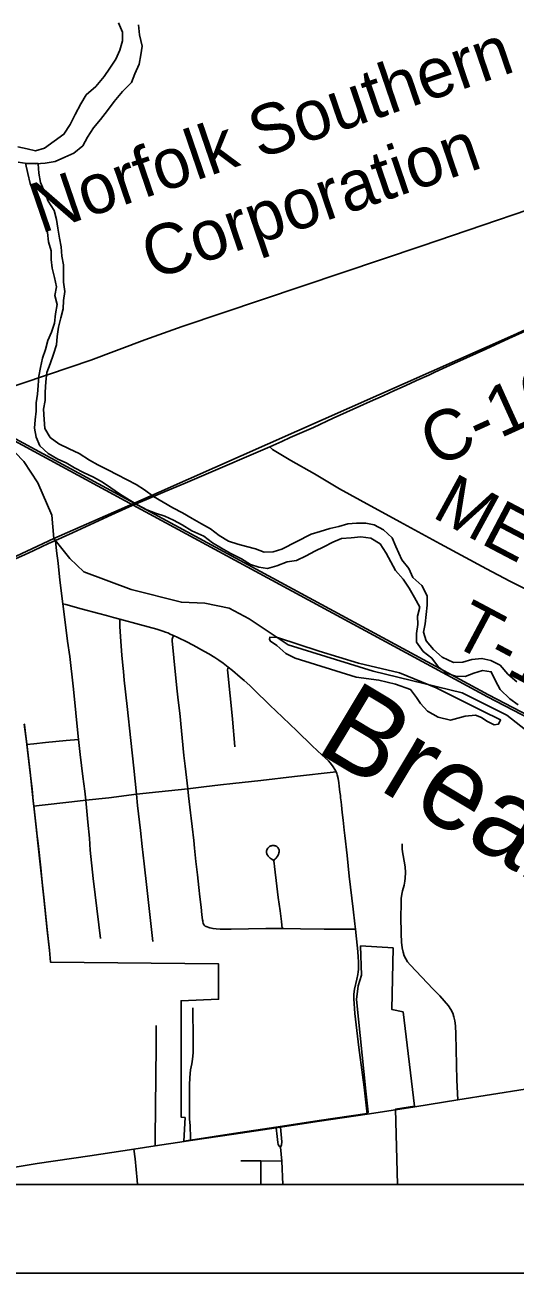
# Model space of a CAD drawing. Extents: x 0 to 34, y 0 to 22.
# Drawn here: x 3.04 to 3.593, y 14 to 15.41 of the extents above; entities that cross this region are included whole.
import ezdxf

# ---------------------------------------------------------------- set-up
doc = ezdxf.new("R2010")
doc.units = 0
for name, color, linetype in [('GM_X_City_Street', 7, 'Continuous'), ('GM_X_Corporation', 7, 'Continuous'), ('GM_X_County_Road', 7, 'Continuous'), ('GM_X_County_Road_Text', 7, 'Continuous'), ('GM_X_Major_River', 7, 'Continuous'), ('GM_X_Minor_Lake', 7, 'Continuous'), ('GM_X_Minor_River', 7, 'Continuous'), ('GM_X_Minor_River_Text', 7, 'Continuous'), ('GM_X_Rail_Line', 7, 'Continuous'), ('GM_X_Rail_Line_Text', 7, 'Continuous'), ('GM_X_State_Route', 7, 'Continuous'), ('GM_X_Township_Road', 7, 'Continuous'), ('GM_X_Township_Road_Text', 7, 'Continuous'), ('SH_Data', 7, 'Continuous')]:
    doc.layers.add(name, color=color, linetype=linetype)

msp = doc.modelspace()

# ---------------------------------------------------------------- linework, layer by layer
at = {"layer": 'GM_X_City_Street'}
for points in [[(3.1866, 14.1436), (3.1865, 14.1524), (3.1876, 14.2567), (3.1876, 14.2797)], [(3.3284, 14.1423), (3.3269, 14.1434), (3.3258, 14.1451), (3.3253, 14.1474), (3.3245, 14.1543), (3.3233, 14.1641)], [(3.3284, 14.1423), (3.3294, 14.145), (3.3296, 14.1484), (3.3281, 14.1649)], [(3.1668, 14.1), (3.1665, 14.1049), (3.164, 14.129), (3.1627, 14.1401)], [(3.3308, 14.1), (3.3298, 14.1265), (3.3284, 14.1423)], [(3.2836, 14.1268), (3.3061, 14.1267), (3.3298, 14.1265)], [(3.3062, 14.1), (3.3061, 14.1196), (3.3061, 14.1267)]]:
    msp.add_lwpolyline(points, dxfattribs=at)
at = {"layer": 'GM_X_Corporation'}
for points in [[(4.718, 17.4962), (3.7119, 17.4934), (3.5801, 17.4924), (3.4708, 17.4915), (3.0456, 17.4894), (2.6352, 17.4929), (2.5812, 17.4925), (2.1449, 17.4882), (2.1, 17.4875), (2.1, 14.1), (5.0398, 14.1)], [(2.1, 14.1), (3.4603, 14.1), (3.458, 14.1851), (3.4797, 14.1885), (3.4667, 14.2951), (3.4539, 14.2978), (3.4555, 14.3673), (3.4187, 14.3696), (3.4199, 14.3367), (3.416, 14.3246), (3.414, 14.3091), (3.4247, 14.2056), (3.4272, 14.1818), (3.4261, 14.1803), (3.372, 14.1723), (3.3279, 14.1654), (3.3231, 14.1647), (3.2753, 14.1575), (3.2265, 14.1501), (3.2191, 14.149), (3.2205, 14.1756), (3.216, 14.1762), (3.2159, 14.3077), (3.2583, 14.3094), (3.2581, 14.3495), (3.0684, 14.3512), (3.0671, 14.365), (3.0646, 14.3881), (3.0607, 14.4246), (3.0593, 14.4383), (3.0572, 14.4586), (3.0541, 14.486), (3.0524, 14.5009), (3.0494, 14.5281), (3.0488, 14.5337), (3.0473, 14.5479), (3.0453, 14.566), (3.0415, 14.5979), (3.0387, 14.6201)]]:
    msp.add_lwpolyline(points, dxfattribs=at)
at = {"layer": 'GM_X_County_Road'}
for points in [[(3.3161, 14.9336), (3.3297, 14.9398), (3.3393, 14.944), (3.3524, 14.9497), (3.3655, 14.9554), (3.3879, 14.9659), (3.4178, 14.9796), (3.4297, 14.9849), (3.4444, 14.9914), (3.4569, 14.9971), (3.4656, 15.0011), (3.4746, 15.0051), (3.482, 15.0084), (3.4959, 15.0147), (3.5017, 15.0174), (3.5115, 15.022), (3.5241, 15.0277), (3.5385, 15.0341), (3.5604, 15.0438), (3.5862, 15.0559), (3.6122, 15.0678)], [(3.0739, 14.8277), (3.0933, 14.8365), (3.1375, 14.8568), (3.1607, 14.8672), (3.1767, 14.8742), (3.1978, 14.883), (3.2204, 14.8925), (3.2441, 14.9027), (3.2652, 14.9117), (3.2899, 14.9223), (3.3161, 14.9336)], [(3.0264, 14.8058), (3.0389, 14.8117), (3.0488, 14.8162), (3.0583, 14.8206), (3.0662, 14.8242), (3.0739, 14.8277)]]:
    msp.add_lwpolyline(points, dxfattribs=at)
at = {"layer": 'GM_X_Major_River'}
for points in [[(3.0319, 15.2553), (3.0418, 15.2538), (3.052, 15.2535), (3.0622, 15.254), (3.0736, 15.256), (3.0845, 15.261), (3.0947, 15.2656), (3.1048, 15.2737), (3.1101, 15.2836), (3.1168, 15.2939), (3.1247, 15.3034), (3.1329, 15.3137), (3.1404, 15.324), (3.1498, 15.3351), (3.1599, 15.3454), (3.1636, 15.3549), (3.1685, 15.3659), (3.1703, 15.3766), (3.1721, 15.3864), (3.169, 15.3993), (3.1677, 15.4103)], [(3.1454, 15.4128), (3.1496, 15.4022), (3.1497, 15.3923), (3.1468, 15.3817), (3.1423, 15.3718), (3.1356, 15.3615), (3.1292, 15.352), (3.1198, 15.3409), (3.1086, 15.3313), (3.1026, 15.3211), (3.0962, 15.3093), (3.0906, 15.2978), (3.0835, 15.2868), (3.0726, 15.2791), (3.0617, 15.2711), (3.0515, 15.2679)], [(3.0515, 15.2679), (3.042, 15.2705), (3.0314, 15.2727)]]:
    msp.add_lwpolyline(points, dxfattribs=at)
at = {"layer": 'GM_X_Minor_Lake'}
msp.add_line((3.4626, 14.6783), (3.4163, 14.6893), dxfattribs=at)
msp.add_lwpolyline([(3.4163, 14.6893), (3.3719, 14.7027), (3.3249, 14.7182), (3.3162, 14.7185), (3.3158, 14.7159), (3.317, 14.714), (3.3242, 14.7091), (3.3341, 14.7001), (3.3447, 14.6949), (3.4138, 14.6734), (3.4392, 14.6698), (3.4581, 14.6654), (3.4752, 14.6595), (3.4821, 14.6504), (3.4863, 14.6436), (3.4943, 14.635), (3.5065, 14.6282), (3.5205, 14.6249), (3.5368, 14.6292), (3.5485, 14.6304), (3.5553, 14.6278), (3.5614, 14.6237), (3.5698, 14.6196), (3.5747, 14.6204), (3.5769, 14.625), (3.556, 14.6354), (3.5043, 14.6612), (3.4626, 14.6783)], dxfattribs=at)
at = {"layer": 'GM_X_Minor_River'}
msp.add_line((3.0543, 15.2536), (3.0403, 15.2541), dxfattribs=at)
for points in [[(3.0403, 15.2541), (3.0426, 15.2425), (3.0454, 15.2311), (3.05, 15.2201), (3.0554, 15.2099), (3.0577, 15.1986), (3.0616, 15.1872), (3.0651, 15.1759), (3.0663, 15.1653), (3.069, 15.1551), (3.0691, 15.1452), (3.0703, 15.1354), (3.0731, 15.1248), (3.075, 15.1145), (3.0732, 15.1047), (3.0759, 15.0944), (3.0741, 15.0838), (3.0731, 15.0732), (3.0694, 15.0633), (3.0653, 15.0538), (3.0627, 15.0435), (3.0594, 15.0336), (3.0572, 15.0234), (3.0554, 15.0135), (3.0543, 15.0029), (3.0536, 14.993), (3.0522, 14.9835), (3.0523, 14.974), (3.0512, 14.9642), (3.0505, 14.9547), (3.0521, 14.9444), (3.0564, 14.9346), (3.0659, 14.926), (3.0765, 14.9196), (3.086, 14.9155), (3.0955, 14.9099), (3.1058, 14.9046), (3.1168, 14.8994), (3.1271, 14.8938), (3.1366, 14.8874), (3.1465, 14.8803), (3.1571, 14.8736), (3.1666, 14.868), (3.1773, 14.8623), (3.1872, 14.8586), (3.1974, 14.8553), (3.2073, 14.8508), (3.2172, 14.8456), (3.2282, 14.8388), (3.2415, 14.8325), (3.2514, 14.825), (3.2616, 14.819), (3.2723, 14.813), (3.2841, 14.807), (3.2943, 14.8007), (3.3038, 14.7977), (3.3137, 14.7963), (3.3242, 14.799), (3.3356, 14.8036), (3.3465, 14.8052), (3.3571, 14.8103), (3.3669, 14.8156), (3.3774, 14.8207), (3.3872, 14.826), (3.3971, 14.8299), (3.408, 14.8308), (3.419, 14.832), (3.4304, 14.8305), (3.441, 14.8238), (3.4475, 14.8136), (3.4583, 14.794), (3.4667, 14.7842), (3.4736, 14.774), (3.4797, 14.7634), (3.4855, 14.7525), (3.4829, 14.7422), (3.4833, 14.7327), (3.4819, 14.7228), (3.482, 14.713), (3.4896, 14.7024), (3.4992, 14.6949), (3.5068, 14.6847), (3.5163, 14.678), (3.5258, 14.6743), (3.5368, 14.674), (3.5466, 14.6778), (3.5564, 14.6809), (3.5663, 14.6795), (3.5713, 14.6693), (3.5766, 14.6595), (3.5873, 14.6489), (3.5968, 14.6422)], [(3.434, 14.8454), (3.4246, 14.8472), (3.4143, 14.8475), (3.4045, 14.8467), (3.3943, 14.8435), (3.3841, 14.8412), (3.3731, 14.8381), (3.363, 14.835), (3.3298, 14.818), (3.32, 14.8149), (3.3097, 14.8144), (3.2999, 14.8185), (3.29, 14.8211), (3.2802, 14.8237), (3.2695, 14.827), (3.2589, 14.8334), (3.249, 14.8409), (3.2391, 14.8465), (3.2285, 14.8525), (3.2174, 14.8589), (3.2068, 14.8648), (3.1847, 14.8776), (3.1745, 14.8851), (3.165, 14.8911), (3.1551, 14.8963), (3.1433, 14.9023), (3.1338, 14.9071), (3.122, 14.9131), (3.1125, 14.9187), (3.1007, 14.9262), (3.0893, 14.9315), (3.0779, 14.9371), (3.068, 14.9442), (3.0619, 14.9544), (3.0614, 14.9646), (3.0606, 14.976), (3.0624, 14.9859), (3.0623, 14.9953), (3.063, 15.0071), (3.0641, 15.0177), (3.0681, 15.0272), (3.0718, 15.0383), (3.0752, 15.0489), (3.0758, 15.0584), (3.0773, 15.0687), (3.0802, 15.0793), (3.0828, 15.0896), (3.0831, 15.099), (3.0845, 15.1093), (3.0829, 15.1195), (3.0832, 15.1294), (3.0832, 15.1392), (3.0812, 15.1491), (3.0804, 15.1597), (3.0784, 15.1695), (3.0768, 15.1805), (3.0752, 15.1904), (3.0725, 15.2006), (3.0656, 15.2112), (3.0621, 15.221), (3.0571, 15.2323), (3.0551, 15.2429), (3.0543, 15.2532), (3.0543, 15.2536)], [(3.5951, 14.668), (3.5852, 14.6766), (3.5764, 14.6868), (3.5658, 14.692), (3.5559, 14.6946), (3.5446, 14.6934), (3.5344, 14.6903), (3.5238, 14.6898), (3.5109, 14.6958), (3.5013, 14.7044), (3.4929, 14.7142), (3.4898, 14.724), (3.4917, 14.7335), (3.4938, 14.7548), (3.4941, 14.7654), (3.4879, 14.7768), (3.4776, 14.7858), (3.4734, 14.796), (3.4654, 14.8058), (3.4584, 14.8209), (3.4546, 14.8307), (3.4447, 14.8398), (3.434, 14.8454)]]:
    msp.add_lwpolyline(points, dxfattribs=at)
at = {"layer": 'GM_X_Rail_Line'}
msp.add_line((3.0723, 14.8299), (3.1616, 14.8692), dxfattribs=at)
for points in [[(3.0008, 14.9933), (3.0663, 15.0153), (3.1139, 15.0316), (3.175, 15.0545), (3.2173, 15.0694), (3.4884, 15.1608), (3.6761, 15.2246)], [(3.1616, 14.8692), (3.5915, 15.0597), (3.6949, 15.1071), (3.7867, 15.1408), (3.9605, 15.1904), (4.0114, 15.1928), (4.2869, 15.2006), (4.3333, 15.1875), (4.5683, 15.0852), (4.7376, 15.04), (4.9105, 14.9964), (5.0522, 14.9674), (5.2111, 14.9619), (5.2822, 14.9606)], [(2.9606, 14.9721), (3.0091, 14.9466), (3.0383, 14.9172), (3.0542, 14.893), (3.0698, 14.8562), (3.0723, 14.8299)], [(4.594, 14.1158), (4.5467, 14.1314), (4.5029, 14.1512), (4.4554, 14.1733), (4.4129, 14.1964), (4.0324, 14.4067), (3.5622, 14.6511), (3.1618, 14.8678), (3.0276, 14.9405)], [(4.5947, 14.118), (4.5475, 14.1335), (4.5039, 14.1533), (4.4565, 14.1754), (4.414, 14.1984), (4.0335, 14.4087), (3.5633, 14.6532), (3.163, 14.8698), (3.0287, 14.9426)], [(2.1, 14.4871), (2.3619, 14.5917), (2.808, 14.7281), (3.0106, 14.8014), (3.0723, 14.8299)], [(3.0723, 14.8299), (3.0901, 14.8076), (3.1059, 14.7922), (3.1597, 14.7724), (3.2163, 14.758), (3.2426, 14.7571), (3.2702, 14.7513), (3.2929, 14.7393), (3.3369, 14.7099), (3.4328, 14.68), (3.5336, 14.6555), (3.5839, 14.6302), (3.6492, 14.5791), (3.7337, 14.5084), (3.8119, 14.4399), (3.8676, 14.3979), (4.0792, 14.1965), (4.1324, 14.1247), (4.148, 14.1)]]:
    msp.add_lwpolyline(points, dxfattribs=at)
at = {"layer": 'GM_X_State_Route'}
for p, q in [((3.4582, 14.1846), (3.4799, 14.1879)), ((3.4263, 14.1797), (3.4582, 14.1846))]:
    msp.add_line(p, q, dxfattribs=at)
for points in [[(3.4799, 14.1879), (3.5286, 14.1957), (3.6048, 14.2077), (3.6481, 14.2147), (3.7802, 14.2348), (3.9245, 14.2567)], [(3.2193, 14.1485), (3.2267, 14.1496), (3.2755, 14.157), (3.3233, 14.1641), (3.3281, 14.1649), (3.3722, 14.1717), (3.4263, 14.1797)], [(3.0084, 14.1167), (3.0191, 14.1181), (3.0352, 14.1206), (3.0535, 14.1236), (3.1129, 14.1326), (3.1627, 14.1401), (3.1866, 14.1436), (3.2193, 14.1485)]]:
    msp.add_lwpolyline(points, dxfattribs=at)
at = {"layer": 'GM_X_Township_Road'}
for points in [[(3.3161, 14.9336), (3.3177, 14.9319), (3.3193, 14.9305), (3.3228, 14.9282), (3.3398, 14.9181), (3.3666, 14.9029), (3.3951, 14.8863), (3.4184, 14.8733), (3.4631, 14.8489), (3.5088, 14.8239), (3.561, 14.7957), (3.5875, 14.7818), (3.6063, 14.7723)], [(3.0823, 14.7563), (3.0791, 14.7829), (3.0769, 14.802), (3.0752, 14.8162), (3.0739, 14.8277)], [(3.0823, 14.7563), (3.0859, 14.7553), (3.103, 14.7507), (3.123, 14.7453), (3.1316, 14.7429), (3.1394, 14.7408), (3.1466, 14.7388)], [(3.1, 14.603), (3.0979, 14.6251), (3.0963, 14.6411), (3.094, 14.6633), (3.0902, 14.6967), (3.0877, 14.7139), (3.0833, 14.7477), (3.0823, 14.7563)], [(3.1466, 14.7388), (3.169, 14.7329), (3.1886, 14.7274), (3.1931, 14.7261), (3.1953, 14.7253), (3.1983, 14.7242), (3.2008, 14.7233), (3.2045, 14.7217), (3.2072, 14.7205)], [(3.1654, 14.541), (3.1625, 14.5704), (3.1592, 14.6019), (3.1549, 14.6402), (3.1518, 14.6699), (3.1507, 14.6799), (3.1501, 14.6865), (3.149, 14.6983), (3.148, 14.7137), (3.1469, 14.7305), (3.1466, 14.7388)], [(3.2235, 14.5473), (3.2206, 14.5726), (3.2192, 14.5849), (3.2144, 14.6325), (3.2127, 14.6472), (3.2112, 14.661), (3.2078, 14.6951), (3.206, 14.7142), (3.2059, 14.7155), (3.206, 14.7164), (3.2062, 14.7174), (3.2072, 14.7205)], [(3.2072, 14.7205), (3.2122, 14.7183), (3.2231, 14.713), (3.2336, 14.7074), (3.2384, 14.7047), (3.2474, 14.6997), (3.2539, 14.6956), (3.2587, 14.6925), (3.2634, 14.6891), (3.2692, 14.6848)], [(3.2766, 14.5947), (3.2758, 14.6041), (3.2747, 14.6169), (3.2739, 14.6261), (3.2686, 14.6783), (3.2685, 14.6815), (3.2687, 14.6831), (3.2692, 14.6848)], [(3.2692, 14.6848), (3.2742, 14.6807), (3.2828, 14.6734), (3.2872, 14.6695), (3.2935, 14.6638), (3.2978, 14.6596), (3.3164, 14.6414)], [(3.3164, 14.6414), (3.3228, 14.6351), (3.3467, 14.6127), (3.3641, 14.5956), (3.3755, 14.5851), (3.3786, 14.5822), (3.3823, 14.5786), (3.3842, 14.5765), (3.3858, 14.5746), (3.3878, 14.5721), (3.3898, 14.5691), (3.3912, 14.5664)], [(3.0417, 14.5973), (3.0389, 14.6196), (3.0388, 14.6206)], [(3.0417, 14.5973), (3.0496, 14.5981), (3.0626, 14.5994), (3.0862, 14.6017), (3.1, 14.603)], [(3.0496, 14.5275), (3.049, 14.5331), (3.0475, 14.5473), (3.0455, 14.5654), (3.0417, 14.5973)], [(3.1082, 14.5342), (3.107, 14.5444), (3.105, 14.5611), (3.1021, 14.5858), (3.1, 14.603)], [(3.2235, 14.5473), (3.2418, 14.5493), (3.2605, 14.5516), (3.2744, 14.5532), (3.306, 14.5565), (3.344, 14.5609), (3.3912, 14.5664)], [(3.4034, 14.4719), (3.4009, 14.4945), (3.4002, 14.5006), (3.399, 14.5117), (3.398, 14.5203), (3.3971, 14.5287), (3.3967, 14.5326), (3.3962, 14.537), (3.3959, 14.5395), (3.3954, 14.5435), (3.3951, 14.5468), (3.3947, 14.55), (3.3941, 14.5541), (3.3934, 14.5588), (3.3924, 14.5629), (3.3918, 14.5646), (3.3912, 14.5664)], [(3.0496, 14.5275), (3.0557, 14.5282), (3.0925, 14.5324), (3.1082, 14.5342), (3.1343, 14.5371), (3.1654, 14.541)], [(3.1654, 14.541), (3.1907, 14.5437), (3.2018, 14.5449), (3.2235, 14.5473)], [(3.184, 14.3745), (3.1805, 14.4053), (3.1771, 14.4355), (3.1743, 14.4624), (3.1721, 14.4819), (3.1701, 14.5001), (3.1668, 14.5284), (3.1654, 14.541)], [(3.2444, 14.3914), (3.2431, 14.3921), (3.2421, 14.3931), (3.2413, 14.3943), (3.2409, 14.3955), (3.2406, 14.3967), (3.2404, 14.398), (3.2402, 14.3992), (3.2395, 14.4047), (3.2385, 14.4133), (3.2371, 14.4251), (3.236, 14.4356), (3.2344, 14.4498), (3.2327, 14.4652), (3.2311, 14.4801), (3.2302, 14.4887), (3.2283, 14.5047), (3.2272, 14.514), (3.2265, 14.5201), (3.2244, 14.5392), (3.2235, 14.5473)], [(3.0527, 14.4995), (3.0526, 14.5004), (3.0496, 14.5275)], [(3.125, 14.3781), (3.123, 14.3935), (3.1166, 14.4458), (3.1134, 14.4778), (3.1123, 14.4914), (3.1107, 14.5094), (3.1089, 14.5261), (3.1082, 14.5342)], [(3.0673, 14.3644), (3.0648, 14.3875), (3.061, 14.424), (3.0595, 14.4377), (3.0574, 14.458), (3.0543, 14.4854), (3.0527, 14.4995)], [(3.5286, 14.1957), (3.5274, 14.2179), (3.5263, 14.2701), (3.5258, 14.2793), (3.5252, 14.2848), (3.5242, 14.2896), (3.5228, 14.2936), (3.5206, 14.2979), (3.5179, 14.3019), (3.5132, 14.3077), (3.5081, 14.3131), (3.5007, 14.3206), (3.4746, 14.3482), (3.4719, 14.3517), (3.4698, 14.3549), (3.4681, 14.3583), (3.4668, 14.3626), (3.4658, 14.3676), (3.4651, 14.3739), (3.4647, 14.3832), (3.4643, 14.4031), (3.4644, 14.4162), (3.4647, 14.4231), (3.4654, 14.4281), (3.4661, 14.4318), (3.4679, 14.4384), (3.4688, 14.4428), (3.4691, 14.4462), (3.4693, 14.4526), (3.469, 14.459), (3.4669, 14.4719), (3.4661, 14.4761), (3.4657, 14.4795), (3.4656, 14.4827), (3.4656, 14.4851)], [(3.3303, 14.3893), (3.3293, 14.3973), (3.3277, 14.4092), (3.3258, 14.4242), (3.3233, 14.4437), (3.3223, 14.4528), (3.3215, 14.4592), (3.3211, 14.4632), (3.3209, 14.4649), (3.3209, 14.4658), (3.3212, 14.4666), (3.3216, 14.4672), (3.3222, 14.4679), (3.3232, 14.4687), (3.3239, 14.4696), (3.3249, 14.471), (3.3259, 14.4731), (3.3265, 14.4748), (3.3267, 14.476), (3.3268, 14.4767), (3.3268, 14.4774), (3.3267, 14.4782), (3.3264, 14.4788), (3.3261, 14.4795), (3.3257, 14.4802), (3.3253, 14.4808), (3.3247, 14.4814), (3.3241, 14.4819), (3.3234, 14.4823), (3.3227, 14.4827), (3.322, 14.4829), (3.3212, 14.4831), (3.3204, 14.4832), (3.3196, 14.4832), (3.3188, 14.4831), (3.318, 14.4829), (3.3172, 14.4827), (3.3165, 14.4823), (3.3158, 14.4819), (3.3151, 14.4814), (3.3146, 14.481), (3.3138, 14.48), (3.3131, 14.4788), (3.3128, 14.478), (3.3126, 14.4772), (3.3125, 14.4764), (3.3125, 14.4755), (3.3126, 14.4748), (3.3127, 14.474), (3.313, 14.4733), (3.3138, 14.4719), (3.3145, 14.4709), (3.3153, 14.47), (3.3159, 14.4694), (3.3166, 14.4688), (3.3178, 14.4679), (3.3183, 14.4675), (3.32, 14.4667)], [(3.4131, 14.3885), (3.4123, 14.3947), (3.4102, 14.4113), (3.4058, 14.4484), (3.4034, 14.4719)], [(3.2444, 14.3914), (3.2483, 14.39), (3.252, 14.3893), (3.2557, 14.3889), (3.26, 14.3886), (3.2643, 14.3885), (3.2727, 14.3887), (3.3117, 14.3894), (3.3303, 14.3893)], [(3.3303, 14.3893), (3.3322, 14.3893), (3.3508, 14.3889), (3.3776, 14.3887), (3.4036, 14.3886), (3.4131, 14.3885)], [(3.4263, 14.1797), (3.4227, 14.2099), (3.4209, 14.2241), (3.4169, 14.2549), (3.4124, 14.2931), (3.4111, 14.3098), (3.4112, 14.3152), (3.4119, 14.3206), (3.4146, 14.332), (3.4156, 14.3373), (3.4161, 14.3403), (3.4163, 14.343), (3.4164, 14.3457), (3.4164, 14.3485), (3.4163, 14.3515), (3.416, 14.357), (3.4156, 14.3634), (3.415, 14.3706), (3.4143, 14.3775), (3.4131, 14.3885)], [(3.2267, 14.1496), (3.2266, 14.1528), (3.2261, 14.1665), (3.2256, 14.1744), (3.2253, 14.1825), (3.2253, 14.2124), (3.2257, 14.221), (3.2267, 14.2297), (3.2279, 14.2364), (3.2289, 14.2418), (3.2295, 14.2487), (3.2297, 14.2548), (3.2296, 14.2635), (3.2291, 14.2995)]]:
    msp.add_lwpolyline(points, dxfattribs=at)
at = {"layer": 'SH_Data'}
for p, q in [((2.1, 14.1), (8.9, 14.1)), ((2, 14), (9, 14))]:
    msp.add_line(p, q, dxfattribs=at)

# ---------------------------------------------------------------- texts
at = {"layer": 'GM_X_County_Road_Text'}
msp.add_text('C-162', height=0.05682, rotation=24.353, dxfattribs=at).set_placement((3.5031, 14.9098))
at = {"layer": 'GM_X_Minor_River_Text'}
msp.add_text('Breakneck', height=0.09474, rotation=328.9739, dxfattribs=at).set_placement((3.3656, 14.5906))
at = {"layer": 'GM_X_Rail_Line_Text'}
for s, rotation, p in [('Norfolk Southern', 18.8751, (3.0574, 15.1744)), ('Corporation', 18.8064, (3.1836, 15.122))]:
    msp.add_text(s, height=0.056629, rotation=rotation, dxfattribs=at).set_placement(p)
at = {"layer": 'GM_X_Township_Road_Text'}
for s, height, rotation, p in [('M', 0.0568, 331.4228, (3.4979, 14.8551)), ('E', 0.0568, 332.31, (3.5529, 14.8251)), ('T-152', 0.05682, 332.0261, (3.5183, 14.712))]:
    msp.add_text(s, height=height, rotation=rotation, dxfattribs=at).set_placement(p)

doc.saveas('drawing.dxf')
